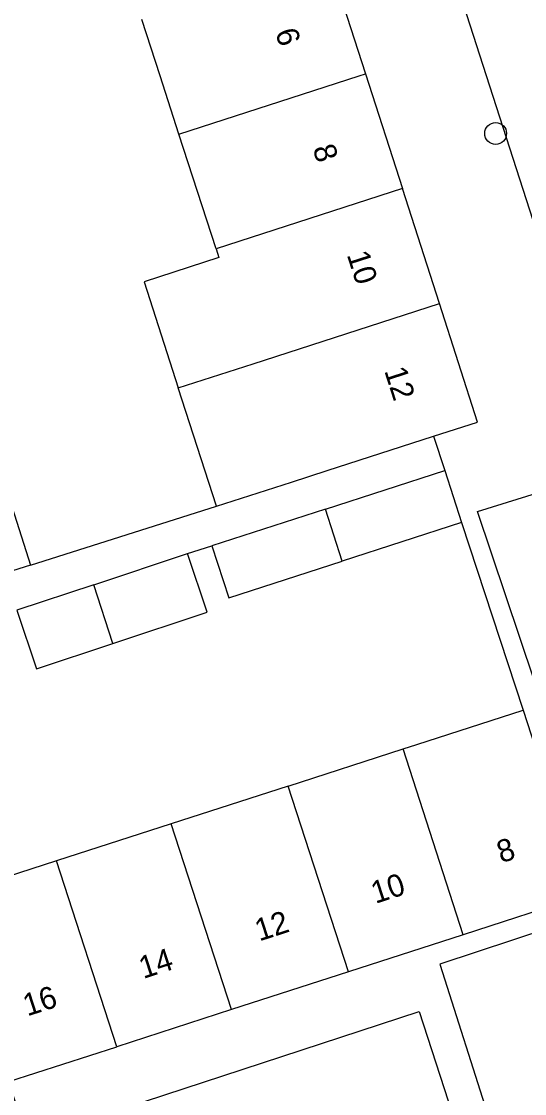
# Model space of a CAD drawing. Extents: x 159377 to 159983, y 382996 to 383595.
# Drawn here: x 159638.52 to 159661.06, y 383204.43 to 383252.43 of the extents above; entities that cross this region are included whole.
import ezdxf

# ---------------------------------------------------------------- set-up
doc = ezdxf.new("R2010")
doc.units = 0
for name, color, linetype in [('IMGEO_Boom', 7, 'Continuous'), ('IMGEO_Muur', 7, 'Continuous'), ('IMGEO_Pand', 7, 'Continuous'), ('IMGEO_Pand_nummerreeks', 7, 'Continuous'), ('IMGEO_Rijbaan_lokaal_open', 7, 'Continuous'), ('IMGEO_Voetpad_open', 7, 'Continuous')]:
    doc.layers.add(name, color=color, linetype=linetype)

msp = doc.modelspace()

# ---------------------------------------------------------------- linework, layer by layer
at = {"layer": 'IMGEO_Boom'}
msp.add_circle((159659.765, 383247.418), 0.489, dxfattribs=at)
at = {"layer": 'IMGEO_Muur'}
msp.add_lwpolyline([(159658.243, 383230), (159660.993, 383221.599)], dxfattribs=at)
at = {"layer": 'IMGEO_Pand'}
for points in [[(159652.281, 383255.229), (159653.942, 383250.092)], [(159645.582, 383247.384), (159644.737, 383249.999), (159643.922, 383252.521)], [(159645.582, 383247.384), (159653.657, 383250), (159653.942, 383250.092)], [(159653.942, 383250.092), (159655.595, 383244.951)], [(159647.243, 383242.246), (159645.582, 383247.384)], [(159655.595, 383244.951), (159647.243, 383242.246)], [(159657.248, 383239.812), (159655.595, 383244.951)], [(159647.243, 383242.246), (159647.367, 383241.861), (159644.015, 383240.777), (159645.552, 383236.023)], [(159645.552, 383236.023), (159648.904, 383237.109), (159657.248, 383239.812)], [(159656.98, 383233.861), (159658.956, 383234.498), (159657.248, 383239.812)], [(159647.261, 383230.725), (159645.552, 383236.023)], [(159647.261, 383230.725), (159650.618, 383231.808), (159652.223, 383232.326), (159656.98, 383233.861)], [(159637.256, 383233.303), (159638.935, 383228.093)], [(159638.935, 383228.093), (159636.782, 383227.422), (159635.103, 383232.633)], [(159652.141, 383230.593), (159657.492, 383232.323)], [(159657.492, 383232.323), (159658.243, 383230)], [(159652.141, 383230.593), (159647.057, 383228.949)], [(159652.894, 383228.27), (159652.141, 383230.593)], [(159658.243, 383230), (159652.894, 383228.27)], [(159647.057, 383228.949), (159647.808, 383226.626), (159652.894, 383228.27)], [(159641.766, 383227.215), (159645.969, 383228.613)], [(159642.621, 383224.579), (159646.844, 383225.983), (159645.969, 383228.613)], [(159641.766, 383227.215), (159638.324, 383226.07)], [(159642.621, 383224.579), (159641.766, 383227.215)], [(159638.324, 383226.07), (159639.199, 383223.44), (159642.621, 383224.579)], [(159655.62, 383219.863), (159656.236, 383220.062), (159660.993, 383221.599)], [(159660.993, 383221.599), (159661.872, 383218.878)], [(159650.472, 383218.199), (159655.62, 383219.863)], [(159658.318, 383211.543), (159655.62, 383219.863)], [(159650.472, 383218.199), (159645.238, 383216.507)], [(159653.168, 383209.879), (159650.472, 383218.199)], [(159645.238, 383216.507), (159640.099, 383214.847)], [(159647.935, 383208.188), (159645.238, 383216.507)], [(159640.099, 383214.847), (159634.971, 383213.189)], [(159642.796, 383206.527), (159640.099, 383214.847)], [(159663.645, 383213.265), (159658.318, 383211.543)], [(159658.318, 383211.543), (159653.168, 383209.879)], [(159653.168, 383209.879), (159647.935, 383208.188)], [(159647.935, 383208.188), (159642.796, 383206.527)], [(159638.218, 383203.162), (159638.514, 383203.258), (159637.962, 383204.965), (159642.796, 383206.527)]]:
    msp.add_lwpolyline(points, dxfattribs=at)
at = {"layer": 'IMGEO_Rijbaan_lokaal_open'}
for points in [[(159663.772, 383234.65), (159663.364, 383235.901), (159663.852, 383236.075), (159659.36, 383250), (159653.786, 383267.274), (159654.055, 383267.387), (159647.551, 383286.019), (159647.315, 383286.718)], [(159670.061, 383215.347), (159670.327, 383214.53), (159657.259, 383210.227), (159659.496, 383203.24), (159636.829, 383195.838)]]:
    msp.add_lwpolyline(points, dxfattribs=at)
at = {"layer": 'IMGEO_Voetpad_open'}
for points in [[(159656.98, 383233.861), (159657.492, 383232.323)], [(159662.767, 383219.167), (159658.956, 383230.496), (159663.614, 383231.939), (159667.406, 383220.667)], [(159638.935, 383228.093), (159647.261, 383230.725)], [(159658.243, 383230), (159660.993, 383221.599)], [(159645.969, 383228.613), (159647.057, 383228.949)], [(159643.164, 383203.797), (159656.336, 383208.097), (159657.833, 383203.511), (159644.662, 383199.21), (159643.164, 383203.797)]]:
    msp.add_lwpolyline(points, dxfattribs=at)

# ---------------------------------------------------------------- texts
at = {"layer": 'IMGEO_Pand_nummerreeks'}
for s, rotation, p in [('6', 287.8724, (159649.88, 383251.955)), ('8', 287.8724, (159651.559, 383246.752)), ('10', 287.8703, (159653.093, 383241.99)), ('12', 287.8703, (159654.768, 383236.795)), ('8', 17.9097, (159660.014, 383214.739)), ('10', 17.9097, (159654.379, 383212.92)), ('12', 17.9097, (159649.178, 383211.238)), ('14', 17.9097, (159643.984, 383209.56)), ('16', 17.9097, (159638.788, 383207.881))]:
    msp.add_text(s, height=1, rotation=rotation, dxfattribs=at).set_placement(p)

doc.saveas('drawing.dxf')
